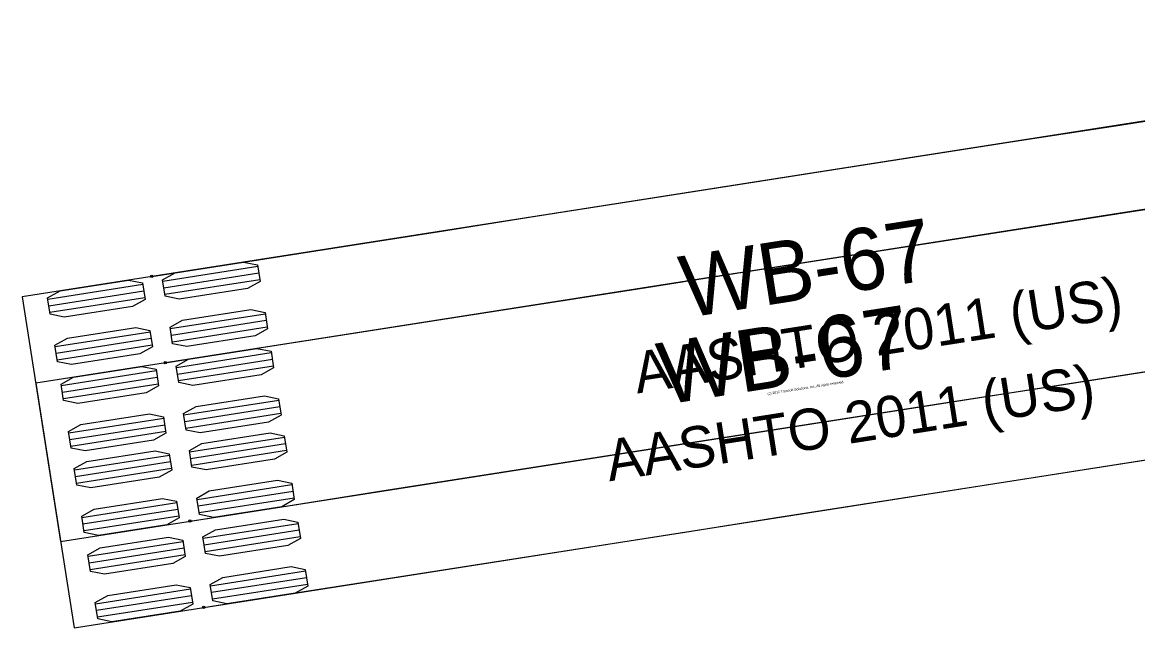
# Model space of a CAD drawing. Extents: x 916040 to 917457, y 328936 to 330267.
# Drawn here: x 916039.76 to 916078.07, y 329685.03 to 329705.81 of the extents above; entities that cross this region are included whole.
import ezdxf

# ---------------------------------------------------------------- set-up
doc = ezdxf.new("R2010")
doc.units = 0
for name, color, linetype in [('EB_LeftontoManchester_WB67', 7, 'Continuous'), ('EB_LeftontoManchester_WB67_v2', 7, 'Continuous'), ('EB_RightontoSaco_WB67_v2', 7, 'Continuous'), ('EB_Thru_WB67', 7, 'Continuous'), ('EB_Thru_WB67_v2', 7, 'Continuous')]:
    doc.layers.add(name, color=color, linetype=linetype)

msp = doc.modelspace()

# ---------------------------------------------------------------- linework, layer by layer
at = {"layer": 'EB_LeftontoManchester_WB67'}
for p, q in [((916092.125, 329704.588), (916039.763, 329696.389)), ((916047.85, 329697.423), (916044.59, 329696.913)), ((916047.886, 329697.197), (916044.625, 329696.686)), ((916043.898, 329696.804), (916040.638, 329696.294)), ((916047.921, 329696.97), (916044.661, 329696.46)), ((916039.763, 329696.389), (916041.078, 329687.991)), ((916043.934, 329696.578), (916040.674, 329696.068)), ((916043.969, 329696.352), (916040.709, 329695.841)), ((916041.078, 329687.991), (916093.44, 329696.19)), ((916048.105, 329695.793), (916044.845, 329695.283)), ((916048.141, 329695.567), (916044.881, 329695.056)), ((916044.154, 329695.174), (916040.893, 329694.664)), ((916048.176, 329695.34), (916044.916, 329694.83)), ((916044.189, 329694.948), (916040.929, 329694.437)), ((916044.225, 329694.722), (916040.964, 329694.211)), ((916048.768, 329691.561), (916045.508, 329691.051)), ((916048.804, 329691.335), (916045.543, 329690.824)), ((916044.816, 329690.943), (916041.556, 329690.432)), ((916048.839, 329691.109), (916045.579, 329690.598)), ((916044.852, 329690.716), (916041.591, 329690.206)), ((916044.887, 329690.49), (916041.627, 329689.979)), ((916049.023, 329689.931), (916045.763, 329689.421)), ((916049.059, 329689.705), (916045.798, 329689.194)), ((916049.094, 329689.478), (916045.834, 329688.968)), ((916045.071, 329689.312), (916041.811, 329688.802)), ((916045.107, 329689.086), (916041.847, 329688.576)), ((916045.142, 329688.86), (916041.882, 329688.349))]:
    msp.add_line(p, q, dxfattribs=at)
for points in [[(916044.209, 329697.085), (916047.503, 329697.601), (916050.797, 329698.117), (916054.091, 329698.632), (916057.385, 329699.148), (916060.679, 329699.663), (916063.974, 329700.179), (916067.268, 329700.693), (916070.563, 329701.208), (916073.858, 329701.722), (916077.153, 329702.235), (916080.449, 329702.748), (916083.744, 329703.26), (916087.04, 329703.771), (916090.336, 329704.282), (916093.633, 329704.791), (916096.929, 329705.299), (916100.227, 329705.806)], [(916045.524, 329688.687), (916048.818, 329689.203), (916052.112, 329689.719), (916055.405, 329690.235), (916058.699, 329690.75), (916061.993, 329691.265), (916065.287, 329691.781), (916068.581, 329692.295), (916071.874, 329692.81), (916075.168, 329693.323), (916078.461, 329693.837), (916081.755, 329694.349), (916085.048, 329694.861), (916088.342, 329695.372), (916091.636, 329695.882), (916094.929, 329696.391), (916098.223, 329696.898), (916101.518, 329697.405)]]:
    msp.add_lwpolyline(points, dxfattribs=at)
for points in [[(916047.841, 329697.479), (916047.93, 329696.914), (916047.5, 329696.673), (916045.153, 329696.305), (916044.67, 329696.404), (916044.581, 329696.969), (916045.011, 329697.211), (916047.358, 329697.578)], [(916043.89, 329696.861), (916043.978, 329696.296), (916043.548, 329696.054), (916041.201, 329695.686), (916040.718, 329695.785), (916040.629, 329696.35), (916041.059, 329696.592), (916043.407, 329696.959)], [(916048.097, 329695.849), (916048.185, 329695.284), (916047.755, 329695.042), (916045.408, 329694.675), (916044.925, 329694.774), (916044.836, 329695.339), (916045.266, 329695.58), (916047.614, 329695.948)], [(916044.145, 329695.23), (916044.233, 329694.665), (916043.804, 329694.424), (916041.456, 329694.056), (916040.973, 329694.155), (916040.885, 329694.72), (916041.314, 329694.962), (916043.662, 329695.329)], [(916048.759, 329691.617), (916048.848, 329691.052), (916048.418, 329690.811), (916046.071, 329690.443), (916045.587, 329690.542), (916045.499, 329691.107), (916045.929, 329691.349), (916048.276, 329691.716)], [(916044.807, 329690.999), (916044.896, 329690.434), (916044.466, 329690.192), (916042.119, 329689.824), (916041.636, 329689.923), (916041.547, 329690.488), (916041.977, 329690.73), (916044.324, 329691.098)], [(916049.015, 329689.987), (916049.103, 329689.422), (916048.673, 329689.18), (916046.326, 329688.813), (916045.843, 329688.912), (916045.754, 329689.477), (916046.184, 329689.719), (916048.531, 329690.086)], [(916045.063, 329689.369), (916045.151, 329688.803), (916044.721, 329688.562), (916042.374, 329688.194), (916041.891, 329688.293), (916041.802, 329688.858), (916042.232, 329689.1), (916044.58, 329689.467)]]:
    msp.add_lwpolyline(points, close=True, dxfattribs=at)
for centre in [(916044.209, 329697.085), (916045.524, 329688.687)]:
    msp.add_circle(centre, 0.0417, dxfattribs=at)
at = {"layer": 'EB_LeftontoManchester_WB67_v2'}
for p, q in [((916092.589, 329701.624), (916040.227, 329693.425)), ((916048.314, 329694.459), (916045.054, 329693.949)), ((916048.35, 329694.233), (916045.089, 329693.722)), ((916048.385, 329694.007), (916045.125, 329693.496)), ((916044.362, 329693.841), (916041.102, 329693.33)), ((916044.398, 329693.614), (916041.138, 329693.104)), ((916040.227, 329693.425), (916041.542, 329685.027)), ((916044.433, 329693.388), (916041.173, 329692.877)), ((916041.542, 329685.027), (916093.904, 329693.226)), ((916048.57, 329692.829), (916045.309, 329692.319)), ((916048.605, 329692.603), (916045.345, 329692.092)), ((916044.618, 329692.21), (916041.357, 329691.7)), ((916048.64, 329692.376), (916045.38, 329691.866)), ((916044.653, 329691.984), (916041.393, 329691.474)), ((916044.689, 329691.758), (916041.428, 329691.247)), ((916049.232, 329688.597), (916045.972, 329688.087)), ((916049.268, 329688.371), (916046.007, 329687.861)), ((916045.28, 329687.979), (916042.02, 329687.468)), ((916049.303, 329688.145), (916046.043, 329687.634)), ((916045.316, 329687.752), (916042.055, 329687.242)), ((916045.351, 329687.526), (916042.091, 329687.015)), ((916049.487, 329686.967), (916046.227, 329686.457)), ((916049.523, 329686.741), (916046.263, 329686.23)), ((916045.536, 329686.349), (916042.275, 329685.838)), ((916049.558, 329686.514), (916046.298, 329686.004)), ((916045.571, 329686.122), (916042.311, 329685.612)), ((916045.606, 329685.896), (916042.346, 329685.385))]:
    msp.add_line(p, q, dxfattribs=at)
for points in [[(916044.673, 329694.121), (916047.977, 329694.639), (916051.282, 329695.156), (916054.587, 329695.673), (916057.892, 329696.191), (916061.196, 329696.708), (916064.501, 329697.225), (916067.807, 329697.741), (916071.112, 329698.257), (916074.418, 329698.773), (916077.71, 329699.286), (916081.003, 329699.798), (916084.297, 329700.309), (916087.591, 329700.819), (916090.886, 329701.327), (916094.181, 329701.833), (916097.478, 329702.336), (916100.776, 329702.835)], [(916045.988, 329685.723), (916049.292, 329686.241), (916052.597, 329686.758), (916055.901, 329687.276), (916059.206, 329687.793), (916062.51, 329688.31), (916065.814, 329688.827), (916069.119, 329689.343), (916072.423, 329689.859), (916075.727, 329690.374), (916079.018, 329690.887), (916082.309, 329691.399), (916085.599, 329691.91), (916088.889, 329692.419), (916092.178, 329692.926), (916095.467, 329693.431), (916098.755, 329693.932), (916102.043, 329694.43)]]:
    msp.add_lwpolyline(points, dxfattribs=at)
for points in [[(916048.306, 329694.515), (916048.394, 329693.95), (916047.964, 329693.709), (916045.617, 329693.341), (916045.134, 329693.44), (916045.045, 329694.005), (916045.475, 329694.247), (916047.822, 329694.614)], [(916044.354, 329693.897), (916044.442, 329693.332), (916044.012, 329693.09), (916041.665, 329692.722), (916041.182, 329692.821), (916041.093, 329693.386), (916041.523, 329693.628), (916043.871, 329693.996)], [(916048.561, 329692.885), (916048.649, 329692.32), (916048.219, 329692.079), (916045.872, 329691.711), (916045.389, 329691.81), (916045.3, 329692.375), (916045.73, 329692.617), (916048.078, 329692.984)], [(916044.609, 329692.267), (916044.697, 329691.701), (916044.268, 329691.46), (916041.92, 329691.092), (916041.437, 329691.191), (916041.349, 329691.756), (916041.778, 329691.998), (916044.126, 329692.365)], [(916049.223, 329688.654), (916049.312, 329688.088), (916048.882, 329687.847), (916046.535, 329687.479), (916046.052, 329687.578), (916045.963, 329688.143), (916046.393, 329688.385), (916048.74, 329688.752)], [(916045.272, 329688.035), (916045.36, 329687.47), (916044.93, 329687.228), (916042.583, 329686.86), (916042.1, 329686.959), (916042.011, 329687.524), (916042.441, 329687.766), (916044.788, 329688.134)], [(916049.479, 329687.023), (916049.567, 329686.458), (916049.137, 329686.217), (916046.79, 329685.849), (916046.307, 329685.948), (916046.218, 329686.513), (916046.648, 329686.755), (916048.996, 329687.122)], [(916045.527, 329686.405), (916045.615, 329685.84), (916045.185, 329685.598), (916042.838, 329685.23), (916042.355, 329685.329), (916042.266, 329685.894), (916042.696, 329686.136), (916045.044, 329686.503)]]:
    msp.add_lwpolyline(points, close=True, dxfattribs=at)
for centre in [(916044.673, 329694.121), (916045.988, 329685.723)]:
    msp.add_circle(centre, 0.0417, dxfattribs=at)
at = {"layer": 'EB_RightontoSaco_WB67_v2'}
for p, q in [((916092.125, 329704.588), (916039.763, 329696.389)), ((916047.85, 329697.423), (916044.59, 329696.913)), ((916047.886, 329697.197), (916044.625, 329696.686)), ((916043.898, 329696.804), (916040.638, 329696.294)), ((916047.921, 329696.97), (916044.661, 329696.46)), ((916039.763, 329696.389), (916041.078, 329687.991)), ((916043.934, 329696.578), (916040.674, 329696.068)), ((916043.969, 329696.352), (916040.709, 329695.841)), ((916041.078, 329687.991), (916093.44, 329696.19)), ((916048.105, 329695.793), (916044.845, 329695.283)), ((916048.141, 329695.567), (916044.881, 329695.056)), ((916044.154, 329695.174), (916040.893, 329694.664)), ((916048.176, 329695.34), (916044.916, 329694.83)), ((916044.189, 329694.948), (916040.929, 329694.437)), ((916044.225, 329694.722), (916040.964, 329694.211)), ((916048.768, 329691.561), (916045.508, 329691.051)), ((916048.804, 329691.335), (916045.543, 329690.824)), ((916044.816, 329690.943), (916041.556, 329690.432)), ((916048.839, 329691.109), (916045.579, 329690.598)), ((916044.852, 329690.716), (916041.591, 329690.206)), ((916044.887, 329690.49), (916041.627, 329689.979)), ((916049.023, 329689.931), (916045.763, 329689.421)), ((916049.059, 329689.705), (916045.798, 329689.194)), ((916049.094, 329689.478), (916045.834, 329688.968)), ((916045.071, 329689.312), (916041.811, 329688.802)), ((916045.107, 329689.086), (916041.847, 329688.576)), ((916045.142, 329688.86), (916041.882, 329688.349))]:
    msp.add_line(p, q, dxfattribs=at)
for points in [[(916044.209, 329697.085), (916047.503, 329697.601), (916050.797, 329698.117), (916054.091, 329698.632), (916057.385, 329699.148), (916060.679, 329699.663), (916063.974, 329700.179), (916067.268, 329700.693), (916070.563, 329701.208), (916073.858, 329701.722), (916077.153, 329702.235), (916080.449, 329702.748), (916083.744, 329703.26), (916087.04, 329703.771), (916090.336, 329704.282), (916093.633, 329704.791), (916096.929, 329705.299), (916100.227, 329705.806)], [(916045.524, 329688.687), (916048.818, 329689.203), (916052.112, 329689.719), (916055.405, 329690.235), (916058.699, 329690.75), (916061.993, 329691.265), (916065.287, 329691.781), (916068.581, 329692.295), (916071.874, 329692.81), (916075.168, 329693.323), (916078.461, 329693.837), (916081.755, 329694.349), (916085.048, 329694.861), (916088.342, 329695.372), (916091.636, 329695.882), (916094.929, 329696.391), (916098.223, 329696.898), (916101.518, 329697.405)]]:
    msp.add_lwpolyline(points, dxfattribs=at)
for points in [[(916047.841, 329697.479), (916047.93, 329696.914), (916047.5, 329696.673), (916045.153, 329696.305), (916044.67, 329696.404), (916044.581, 329696.969), (916045.011, 329697.211), (916047.358, 329697.578)], [(916043.89, 329696.861), (916043.978, 329696.296), (916043.548, 329696.054), (916041.201, 329695.686), (916040.718, 329695.785), (916040.629, 329696.35), (916041.059, 329696.592), (916043.407, 329696.959)], [(916048.097, 329695.849), (916048.185, 329695.284), (916047.755, 329695.042), (916045.408, 329694.675), (916044.925, 329694.774), (916044.836, 329695.339), (916045.266, 329695.58), (916047.614, 329695.948)], [(916044.145, 329695.23), (916044.233, 329694.665), (916043.804, 329694.424), (916041.456, 329694.056), (916040.973, 329694.155), (916040.885, 329694.72), (916041.314, 329694.962), (916043.662, 329695.329)], [(916048.759, 329691.617), (916048.848, 329691.052), (916048.418, 329690.811), (916046.071, 329690.443), (916045.587, 329690.542), (916045.499, 329691.107), (916045.929, 329691.349), (916048.276, 329691.716)], [(916044.807, 329690.999), (916044.896, 329690.434), (916044.466, 329690.192), (916042.119, 329689.824), (916041.636, 329689.923), (916041.547, 329690.488), (916041.977, 329690.73), (916044.324, 329691.098)], [(916049.015, 329689.987), (916049.103, 329689.422), (916048.673, 329689.18), (916046.326, 329688.813), (916045.843, 329688.912), (916045.754, 329689.477), (916046.184, 329689.719), (916048.531, 329690.086)], [(916045.063, 329689.369), (916045.151, 329688.803), (916044.721, 329688.562), (916042.374, 329688.194), (916041.891, 329688.293), (916041.802, 329688.858), (916042.232, 329689.1), (916044.58, 329689.467)]]:
    msp.add_lwpolyline(points, close=True, dxfattribs=at)
for centre in [(916044.209, 329697.085), (916045.524, 329688.687)]:
    msp.add_circle(centre, 0.0417, dxfattribs=at)
at = {"layer": 'EB_Thru_WB67'}
for p, q in [((916092.125, 329704.588), (916039.763, 329696.389)), ((916047.85, 329697.423), (916044.59, 329696.913)), ((916047.886, 329697.197), (916044.625, 329696.686)), ((916043.898, 329696.804), (916040.638, 329696.294)), ((916047.921, 329696.97), (916044.661, 329696.46)), ((916039.763, 329696.389), (916041.078, 329687.991)), ((916043.934, 329696.578), (916040.674, 329696.068)), ((916043.969, 329696.352), (916040.709, 329695.841)), ((916041.078, 329687.991), (916093.44, 329696.19)), ((916048.105, 329695.793), (916044.845, 329695.283)), ((916048.141, 329695.567), (916044.881, 329695.056)), ((916044.154, 329695.174), (916040.893, 329694.664)), ((916048.176, 329695.34), (916044.916, 329694.83)), ((916044.189, 329694.948), (916040.929, 329694.437)), ((916044.225, 329694.722), (916040.964, 329694.211)), ((916048.768, 329691.561), (916045.508, 329691.051)), ((916048.804, 329691.335), (916045.543, 329690.824)), ((916044.816, 329690.943), (916041.556, 329690.432)), ((916048.839, 329691.109), (916045.579, 329690.598)), ((916044.852, 329690.716), (916041.591, 329690.206)), ((916044.887, 329690.49), (916041.627, 329689.979)), ((916049.023, 329689.931), (916045.763, 329689.421)), ((916049.059, 329689.705), (916045.798, 329689.194)), ((916049.094, 329689.478), (916045.834, 329688.968)), ((916045.071, 329689.312), (916041.811, 329688.802)), ((916045.107, 329689.086), (916041.847, 329688.576)), ((916045.142, 329688.86), (916041.882, 329688.349))]:
    msp.add_line(p, q, dxfattribs=at)
for points in [[(916044.209, 329697.085), (916047.503, 329697.601), (916050.797, 329698.117), (916054.091, 329698.632), (916057.385, 329699.148), (916060.679, 329699.663), (916063.974, 329700.179), (916067.268, 329700.693), (916070.563, 329701.208), (916073.858, 329701.722), (916077.153, 329702.235), (916080.449, 329702.748), (916083.744, 329703.26), (916087.04, 329703.771), (916090.336, 329704.282), (916093.633, 329704.791), (916096.929, 329705.299), (916100.227, 329705.806)], [(916045.524, 329688.687), (916048.818, 329689.203), (916052.112, 329689.719), (916055.405, 329690.235), (916058.699, 329690.75), (916061.993, 329691.265), (916065.287, 329691.781), (916068.581, 329692.295), (916071.874, 329692.81), (916075.168, 329693.323), (916078.461, 329693.837), (916081.755, 329694.349), (916085.048, 329694.861), (916088.342, 329695.372), (916091.636, 329695.882), (916094.929, 329696.391), (916098.223, 329696.898), (916101.518, 329697.405)]]:
    msp.add_lwpolyline(points, dxfattribs=at)
for points in [[(916047.841, 329697.479), (916047.93, 329696.914), (916047.5, 329696.673), (916045.153, 329696.305), (916044.67, 329696.404), (916044.581, 329696.969), (916045.011, 329697.211), (916047.358, 329697.578)], [(916043.89, 329696.861), (916043.978, 329696.296), (916043.548, 329696.054), (916041.201, 329695.686), (916040.718, 329695.785), (916040.629, 329696.35), (916041.059, 329696.592), (916043.407, 329696.959)], [(916048.097, 329695.849), (916048.185, 329695.284), (916047.755, 329695.042), (916045.408, 329694.675), (916044.925, 329694.774), (916044.836, 329695.339), (916045.266, 329695.58), (916047.614, 329695.948)], [(916044.145, 329695.23), (916044.233, 329694.665), (916043.804, 329694.424), (916041.456, 329694.056), (916040.973, 329694.155), (916040.885, 329694.72), (916041.314, 329694.962), (916043.662, 329695.329)], [(916048.759, 329691.617), (916048.848, 329691.052), (916048.418, 329690.811), (916046.071, 329690.443), (916045.587, 329690.542), (916045.499, 329691.107), (916045.929, 329691.349), (916048.276, 329691.716)], [(916044.807, 329690.999), (916044.896, 329690.434), (916044.466, 329690.192), (916042.119, 329689.824), (916041.636, 329689.923), (916041.547, 329690.488), (916041.977, 329690.73), (916044.324, 329691.098)], [(916049.015, 329689.987), (916049.103, 329689.422), (916048.673, 329689.18), (916046.326, 329688.813), (916045.843, 329688.912), (916045.754, 329689.477), (916046.184, 329689.719), (916048.531, 329690.086)], [(916045.063, 329689.369), (916045.151, 329688.803), (916044.721, 329688.562), (916042.374, 329688.194), (916041.891, 329688.293), (916041.802, 329688.858), (916042.232, 329689.1), (916044.58, 329689.467)]]:
    msp.add_lwpolyline(points, close=True, dxfattribs=at)
for centre in [(916044.209, 329697.085), (916045.524, 329688.687)]:
    msp.add_circle(centre, 0.0417, dxfattribs=at)
at = {"layer": 'EB_Thru_WB67_v2'}
for p, q in [((916092.589, 329701.624), (916040.227, 329693.425)), ((916048.314, 329694.459), (916045.054, 329693.949)), ((916048.35, 329694.233), (916045.089, 329693.722)), ((916048.385, 329694.007), (916045.125, 329693.496)), ((916044.362, 329693.841), (916041.102, 329693.33)), ((916044.398, 329693.614), (916041.138, 329693.104)), ((916040.227, 329693.425), (916041.542, 329685.027)), ((916044.433, 329693.388), (916041.173, 329692.877)), ((916041.542, 329685.027), (916093.904, 329693.226)), ((916048.57, 329692.829), (916045.309, 329692.319)), ((916048.605, 329692.603), (916045.345, 329692.092)), ((916044.618, 329692.21), (916041.357, 329691.7)), ((916048.64, 329692.376), (916045.38, 329691.866)), ((916044.653, 329691.984), (916041.393, 329691.474)), ((916044.689, 329691.758), (916041.428, 329691.247)), ((916049.232, 329688.597), (916045.972, 329688.087)), ((916049.268, 329688.371), (916046.007, 329687.861)), ((916045.28, 329687.979), (916042.02, 329687.468)), ((916049.303, 329688.145), (916046.043, 329687.634)), ((916045.316, 329687.752), (916042.055, 329687.242)), ((916045.351, 329687.526), (916042.091, 329687.015)), ((916049.487, 329686.967), (916046.227, 329686.457)), ((916049.523, 329686.741), (916046.263, 329686.23)), ((916045.536, 329686.349), (916042.275, 329685.838)), ((916049.558, 329686.514), (916046.298, 329686.004)), ((916045.571, 329686.122), (916042.311, 329685.612)), ((916045.606, 329685.896), (916042.346, 329685.385))]:
    msp.add_line(p, q, dxfattribs=at)
for points in [[(916044.673, 329694.121), (916047.977, 329694.639), (916051.282, 329695.156), (916054.587, 329695.673), (916057.892, 329696.191), (916061.196, 329696.708), (916064.501, 329697.225), (916067.807, 329697.741), (916071.112, 329698.257), (916074.418, 329698.773), (916077.713, 329699.286), (916081.009, 329699.799), (916084.306, 329700.311), (916087.603, 329700.821), (916090.9, 329701.33), (916094.199, 329701.836), (916097.499, 329702.339), (916100.8, 329702.838)], [(916045.988, 329685.723), (916049.292, 329686.241), (916052.597, 329686.758), (916055.901, 329687.276), (916059.206, 329687.793), (916062.51, 329688.31), (916065.814, 329688.827), (916069.119, 329689.343), (916072.423, 329689.859), (916075.727, 329690.374), (916079.021, 329690.888), (916082.315, 329691.4), (916085.608, 329691.911), (916088.901, 329692.421), (916092.193, 329692.928), (916095.485, 329693.433), (916098.776, 329693.935), (916102.067, 329694.433)]]:
    msp.add_lwpolyline(points, dxfattribs=at)
for points in [[(916048.306, 329694.515), (916048.394, 329693.95), (916047.964, 329693.709), (916045.617, 329693.341), (916045.134, 329693.44), (916045.045, 329694.005), (916045.475, 329694.247), (916047.822, 329694.614)], [(916044.354, 329693.897), (916044.442, 329693.332), (916044.012, 329693.09), (916041.665, 329692.722), (916041.182, 329692.821), (916041.093, 329693.386), (916041.523, 329693.628), (916043.871, 329693.996)], [(916048.561, 329692.885), (916048.649, 329692.32), (916048.219, 329692.079), (916045.872, 329691.711), (916045.389, 329691.81), (916045.3, 329692.375), (916045.73, 329692.617), (916048.078, 329692.984)], [(916044.609, 329692.267), (916044.697, 329691.701), (916044.268, 329691.46), (916041.92, 329691.092), (916041.437, 329691.191), (916041.349, 329691.756), (916041.778, 329691.998), (916044.126, 329692.365)], [(916049.223, 329688.654), (916049.312, 329688.088), (916048.882, 329687.847), (916046.535, 329687.479), (916046.052, 329687.578), (916045.963, 329688.143), (916046.393, 329688.385), (916048.74, 329688.752)], [(916045.272, 329688.035), (916045.36, 329687.47), (916044.93, 329687.228), (916042.583, 329686.86), (916042.1, 329686.959), (916042.011, 329687.524), (916042.441, 329687.766), (916044.788, 329688.134)], [(916049.479, 329687.023), (916049.567, 329686.458), (916049.137, 329686.217), (916046.79, 329685.849), (916046.307, 329685.948), (916046.218, 329686.513), (916046.648, 329686.755), (916048.996, 329687.122)], [(916045.527, 329686.405), (916045.615, 329685.84), (916045.185, 329685.598), (916042.838, 329685.23), (916042.355, 329685.329), (916042.266, 329685.894), (916042.696, 329686.136), (916045.044, 329686.503)]]:
    msp.add_lwpolyline(points, close=True, dxfattribs=at)
for centre in [(916044.673, 329694.121), (916045.988, 329685.723)]:
    msp.add_circle(centre, 0.0417, dxfattribs=at)

# ---------------------------------------------------------------- texts
at = {"layer": 'EB_LeftontoManchester_WB67'}
for s, height, p in [('WB-67', 2.125, (916062.553, 329695.655)), ('AASHTO 2011 (US)', 1.41667, (916060.879, 329693.063))]:
    msp.add_text(s, height=height, rotation=8.8989, dxfattribs=at).set_placement(p)
at = {"layer": 'EB_LeftontoManchester_WB67_v2'}
for s, height, p in [('WB-67', 2.125, (916061.791, 329692.672)), ('AASHTO 2011 (US)', 1.41667, (916059.922, 329690.049)), ('(c) 2016 Transoft Solutions, Inc. All rights reserved.', 0.085, (916065.36, 329693.016))]:
    msp.add_text(s, height=height, rotation=8.8989, dxfattribs=at).set_placement(p)
at = {"layer": 'EB_RightontoSaco_WB67_v2'}
for s, height, p in [('WB-67', 2.125, (916062.553, 329695.655)), ('AASHTO 2011 (US)', 1.41667, (916060.879, 329693.063))]:
    msp.add_text(s, height=height, rotation=8.8989, dxfattribs=at).set_placement(p)
at = {"layer": 'EB_Thru_WB67'}
for s, height, p in [('WB-67', 2.125, (916062.553, 329695.655)), ('AASHTO 2011 (US)', 1.41667, (916060.879, 329693.063))]:
    msp.add_text(s, height=height, rotation=8.8989, dxfattribs=at).set_placement(p)
at = {"layer": 'EB_Thru_WB67_v2'}
for s, height, p in [('WB-67', 2.125, (916061.791, 329692.672)), ('AASHTO 2011 (US)', 1.41667, (916059.922, 329690.049)), ('(c) 2016 Transoft Solutions, Inc. All rights reserved.', 0.085, (916065.36, 329693.016))]:
    msp.add_text(s, height=height, rotation=8.8989, dxfattribs=at).set_placement(p)

doc.saveas('drawing.dxf')
